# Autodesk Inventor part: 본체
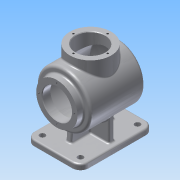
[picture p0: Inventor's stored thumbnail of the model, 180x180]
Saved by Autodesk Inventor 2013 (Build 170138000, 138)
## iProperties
Created: 2016-09
Part Number: 본체
Material: 알루미늄 6061
Document SubType Name: Modeling
Designer: Administrator
Density: 2.71 g/cm^3
Mass: 972.179 g
Surface Area: 1283.63 cm^2
Volume: 358.738 cm^3
Author: Administrator
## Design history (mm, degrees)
sketch "스케치1"
  geometry: L1 (-67.5, 50)-(67.5, 50); L2 (67.5, 50)-(67.5, -50); L3 (67.5, -50)-(-67.5, -50); L4 (-67.5, -50)-(-67.5, 50); L5 (67.5, -50)-(-67.5, 50); 2 further points
  constraints: 10 end point, 2 parallel, 1 coincident, 1 horizontal, 1 midpoint, 1 perpendicular
  dimensions: "d0" = 135 distance of L1.start L1.end; "d2" = 100 distance of L1.end L2.end
extrude "돌출1" new body sketch "스케치1" distance "d3" = 10; taper "d4" = 0 deg
fillet "모깎기1" dims "d5" = 15
hole "구멍1" diameter "d8" = 10; stored, may be unused: countersink angle "d12" = 90 deg, drill point angle "d14" = 0 deg; dims "d6" = 10, "d7" = 10, "d9" = 6, "d10" = 4, "d11" = 2, "d13" = 8
hole "구멍2" diameter "d17" = 10; stored, may be unused: countersink angle "d21" = 90 deg, drill point angle "d23" = 0 deg; dims "d15" = 10, "d16" = 10, "d18" = 6, "d19" = 4, "d20" = 2, "d22" = 8
hole "구멍3" diameter "d26" = 10; stored, may be unused: countersink angle "d30" = 90 deg, drill point angle "d32" = 0 deg; dims "d24" = 10, "d25" = 10, "d27" = 6, "d28" = 4, "d29" = 2, "d31" = 8
hole "구멍4" diameter "d35" = 10; stored, may be unused: countersink angle "d39" = 90 deg, drill point angle "d41" = 0 deg; dims "d33" = 10, "d34" = 10, "d36" = 6, "d37" = 4, "d38" = 2, "d40" = 8
fillet "모깎기2" dims "d42" = 3
sketch "스케치3"
  geometry: L1 (-64.5, 10)-(64.5, 10) reference; L2 (67.5, 7)-(67.5, 0) reference; L3 (67.5, 0)-(-67.5, 0) reference; L4 (-67.5, 0)-(-67.5, 7) reference; L5 (0, 0)-(0, 82); L6 (-44, 132)-(46.374, 132); L7 (61, 132)-(61, 82); L8 (61, 82)-(-61, 82); L9 (-61, 82)-(-61, 132); L10 (-61, 120)-(-49, 120); L11 (-49, 120)-(-49, 127); L12 (46.374, 129)-(-44, 129); L13 (-46, 127)-(-46, 82); L14 (-61, 82)-(61, 82); A1 r 3 centre (-64.5, 7) between (-64.5, 10) and (-67.5, 7) reference; A2 r 3 centre (64.5, 7) between (67.5, 7) and (64.5, 10) reference; A3 r 115 centre (-54, 82) between (26.629, 0) and (35.672, 10); A4 r 115 centre (-54, 82) between (61, 82) and (50.937, 129.045); A5 r 112 centre (-54, 82) between (58, 82) and (48.199, 127.818); A6 r 2 centre (-44, 127) between (-44, 129) and (-46, 127); A7 r 2 centre (46.374, 127) between (48.199, 127.818) and (46.374, 129); A8 r 5 centre (-44, 127) between (-44, 132) and (-49, 127); A9 r 5 centre (46.374, 127) between (50.937, 129.045) and (46.374, 132); 3 further points
  constraints: 20 end point, 16 point on circle, 10 point on line, 9 tangent, 7 centre point, 5 perpendicular, 3 parallel, 2 equal radius, 1 collinear, 1 horizontal, 1 midpoint
  dimensions: "d44" = 82 distance of L5.end L5.start; "d45" = 122 distance of L9.end L7.start; "d47" = 76 diameter of L10 L8; "d48" = 100 diameter of L6 L8; "d50" = 115 radius of A4; "d51" = 3 radial gap between concentric circles of A4 A5; "d52" = 3 distance between parallel lines of L6 L12; "d53" = 3 distance between parallel lines of L11 L13; "d54" = 2 radius of A6; "d55" = 5 radius of A8; "d56" = 12 distance of L10.start L10.end
revolve "회전1" sketch "스케치3" stored, may be unused: angle "d57" = 90 deg
sketch "스케치4"
  geometry: L1 (-64.5, 10)-(64.5, 10) reference; L2 (67.5, 7)-(67.5, 0) reference; L3 (67.5, 0)-(-67.5, 0) reference; L4 (-67.5, 0)-(-67.5, 7) reference; L5 (-61, 44)-(-61, 120) reference; L6 (-61, 120)-(-49, 120) reference; L7 (-49, 120)-(-49, 127) reference; L8 (-44, 132)-(46.374, 132) reference; L9 (46.374, 32)-(-44, 32) reference; L10 (-49, 37)-(-49, 44) reference; L11 (-49, 44)-(-61, 44) reference; L12 (46.374, 129)-(-44, 129); L13 (-46, 127)-(-46, 117); L14 (-46, 117)-(-58, 117); L15 (-58, 117)-(-58, 82); L16 (-58, 82)-(58, 82); L17 (-46, 117)-(-46, 82); A1 r 3 centre (-64.5, 7) between (-64.5, 10) and (-67.5, 7) reference; A2 r 3 centre (64.5, 7) between (67.5, 7) and (64.5, 10) reference; A3 r 5 centre (-44, 127) between (-44, 132) and (-49, 127) reference; A4 r 5 centre (46.374, 127) between (50.937, 129.045) and (46.374, 132) reference; A5 r 115 centre (-54, 82) between (50.937, 34.955) and (50.937, 129.045) reference; A6 r 5 centre (46.374, 37) between (46.374, 32) and (50.937, 34.955) reference; A7 r 5 centre (-44, 37) between (-49, 37) and (-44, 32) reference; A8 r 2 centre (-44, 127) between (-44, 129) and (-46, 127); A9 r 112 centre (-54, 82) between (58, 82) and (48.199, 127.818); A10 r 2 centre (46.374, 127) between (48.199, 127.818) and (46.374, 129); 1 further point
  constraints: 12 end point, 6 point on circle, 3 centre point, 1 point on line, 3 other
  dimensions: "d58" = 3 distance between parallel lines of L12 L8
revolve "회전2" sketch "스케치4" stored, may be unused: angle "d59" = 90 deg
hole "구멍5" diameter "d62" = 54; stored, may be unused: countersink angle "d66" = 90 deg, drill point angle "d68" = 0 deg; dims "d60" = 10, "d61" = 10, "d63" = 6, "d64" = 4, "d65" = 2, "d67" = 20
node "작업 평면1"
sketch "스케치5"
  geometry: L1 (-46.374, 50)-(-46.374, -50) reference; L2 (49, 45)-(49, -45) reference; L3 (52.5, 50)-(-52.5, 50) reference; L4 (44, -50)-(-46.374, -50) reference; C1 r 38 at (-1, 0)
  constraints: 1 centre point
  dimensions: "d70" = 76 diameter of C1; "d133" = 50 distance from line of L2 C1.centre; "d134" = 50 distance from line of L4 C1.centre
extrude "돌출2" join sketch "스케치5" stored distance "d71" = 10; taper "d72" = 0 deg
hole "구멍6" diameter "d75" = 54; stored, may be unused: countersink angle "d79" = 90 deg, drill point angle "d81" = 0 deg; dims "d73" = 10, "d74" = 10, "d76" = 6, "d77" = 4, "d78" = 2, "d80" = 50
fillet "모깎기3" dims "d82" = 3
chamfer "모따기1" distance "d83" = 1; stored, may be unused: second distance "d84" = 2, angle "d85" = 45 deg
sketch "스케치6"
  geometry: L1 (-31.5, 0)-(33.5, 0); C1 r 28 at (0, 0) reference; C2 r 38 at (0, 0) reference; 3 further points
  constraints: 2 coincident, 2 end point, 1 horizontal, 1 midpoint
  dimensions: "d86" = 65 distance of L1.start L1.end
hole "구멍7" sketch "스케치6" at (-31.5, 0) diameter "d88" = 3.459; stored, may be unused: countersink angle "d92" = 90 deg, drill point angle "d94" = 118 deg; dims "d89" = 8, "d90" = 4, "d91" = 2, "d93" = 10
sketch "스케치7"
  geometry: L1 (75, 47.359)-(82, 47.359) reference; L2 (82, 47.359)-(82, -47.359) reference; L3 (82, -47.359)-(75, -47.359) reference; L4 (72, -43.471)-(72, 43.471) reference; L5 (32.5, 0)-(-32.5, 0); C1 r 28 at (0, 0) reference; C2 r 38 at (0, 0) reference; 3 further points
  constraints: 2 coincident, 2 end point, 1 midpoint, 1 perpendicular, 2 other
  dimensions: "d98" = 65 distance of L5.start L5.end
hole "구멍8" sketch "스케치7" at (-32.5, 0) diameter "d100" = 3.459; stored, may be unused: countersink angle "d104" = 90 deg, drill point angle "d106" = 118 deg; dims "d101" = 8, "d102" = 4, "d103" = 2, "d105" = 10
sketch "스케치9"
  geometry: L1 (-46, 127)-(-46, 109) reference; L2 (-46, 109)-(-60, 109) reference; L3 (-60, 109)-(-61, 110) reference; L4 (-61, 110)-(-61, 112.77) reference; L5 (-61, 112.77)-(-51, 112.77) reference; L6 (-51, 112.77)-(-49.961, 114.5) reference; L7 (-49.961, 114.5)-(-51, 116.23) reference; L8 (-51, 116.23)-(-61, 116.23) reference; L9 (-61, 116.23)-(-61, 120) reference; L10 (-61, 120)-(-52, 120) reference; L11 (-49, 123)-(-49, 127) reference; L12 (-44, 132)-(-40, 132) reference; L13 (-37, 135)-(-37, 147) reference; L14 (-37, 147)-(-32.23, 147) reference; L15 (-32.23, 147)-(-32.23, 137) reference; L16 (-32.23, 137)-(-30.5, 135.961) reference; L17 (-30.5, 135.961)-(-28.771, 137) reference; L18 (-28.771, 137)-(-28.771, 147) reference; L19 (-28.771, 147)-(-27, 147) reference; L20 (-27, 147)-(-26, 146) reference; L21 (-26, 146)-(-26, 129) reference; L22 (-26, 129)-(-44, 129) reference; L23 (-64.5, 10)-(64.5, 10) reference; L24 (46.374, 32)-(-44, 32) reference; L25 (-49, 37)-(-49, 41) reference; L26 (-52, 44)-(-61, 44) reference; L27 (-61, 44)-(-61, 47.77) reference; L28 (-61, 47.77)-(-51, 47.77) reference; L29 (-51, 47.77)-(-49.961, 49.5) reference; L30 (-49.961, 49.5)-(-51, 51.229) reference; L31 (-51, 51.229)-(-61, 51.229) reference; L32 (-61, 51.229)-(-61, 54) reference; L33 (-61, 54)-(-60, 55) reference; L34 (-60, 55)-(-46, 55) reference; L35 (-46, 55)-(-46, 37) reference; L36 (-44, 35)-(46.374, 35) reference; L37 (46.374, 129)-(28, 129) reference; L38 (28, 129)-(28, 146) reference; L39 (28, 146)-(29, 147) reference; L40 (29, 147)-(30.77, 147) reference; L41 (30.77, 147)-(30.77, 137) reference; L42 (30.77, 137)-(32.5, 135.961) reference; L43 (32.5, 135.961)-(34.23, 137) reference; L44 (34.23, 137)-(34.23, 147) reference; L45 (34.23, 147)-(39, 147) reference; L46 (39, 147)-(39, 135) reference; L47 (42, 132)-(46.374, 132) reference; L48 (67.5, 7)-(67.5, 0) reference; L49 (67.5, 0)-(-67.5, 0) reference; L50 (-67.5, 0)-(-67.5, 7) reference; L51 (-38.075, 32)-(-40, 10); L52 (0, 0)-(0, 67.844); L53 (38.075, 32)-(40, 10); A1 r 2 centre (-44, 127) between (-44, 129) and (-46, 127) reference; A2 r 3 centre (-52, 123) between (-52, 120) and (-49, 123) reference; A3 r 5 centre (-44, 127) between (-44, 132) and (-49, 127) reference; A4 r 3 centre (-64.5, 7) between (-64.5, 10) and (-67.5, 7) reference; A5 r 5 centre (-44, 37) between (-49, 37) and (-44, 32) reference; A6 r 3 centre (-52, 41) between (-49, 41) and (-52, 44) reference; A7 r 2 centre (-44, 37) between (-46, 37) and (-44, 35) reference; A8 r 2 centre (46.374, 37) between (46.374, 35) and (48.199, 36.182) reference; A9 r 112 centre (-54, 82) between (48.199, 36.182) and (48.199, 127.818) reference; A10 r 2 centre (46.374, 127) between (48.199, 127.818) and (46.374, 129) reference; A11 r 5 centre (46.374, 127) between (50.937, 129.045) and (46.374, 132) reference; A12 r 115 centre (-54, 82) between (50.937, 34.955) and (50.937, 129.045) reference; A13 r 5 centre (46.374, 37) between (46.374, 32) and (50.937, 34.955) reference; A14 r 3 centre (64.5, 7) between (67.5, 7) and (64.5, 10) reference
  constraints: 6 end point, 2 point on line, 2 symmetric about line, 1 parallel, 2 other
  dimensions: "d114" = 40 horizontal distance of L52.start L51.end; "d115" = 95 deg angle of L23 L51
  node "절단 모서리 투영6"
node "작업 평면2"
sketch "스케치10"
  geometry: L1 (43.292, 7)-(43.292, 0) reference; L2 (43.292, 0)-(-43.292, 0) reference; L3 (-43.292, 0)-(-43.292, 7) reference; L4 (-35, 9.958)-(35, 9.958) reference; L5 (35, 0)-(-35, 0) reference; L6 (-26.132, 94.195)-(26.132, 94.195); L7 (26.132, 94.195)-(26.132, 69.805); L8 (26.132, 69.805)-(-26.132, 69.805); L9 (-26.132, 69.805)-(-26.132, 94.195); L10 (-26.132, 82)-(26.132, 82); L11 (0, 94.195)-(0, 69.805); L12 (0, 82)-(0, 0); C1 r 50 at (0, 82) reference
  constraints: 6 end point, 5 midpoint, 2 collinear, 4 other
feature "엠보싱1" sketch "스케치10" dims "d0" = 135, "d2" = 100, "d24" = 10, "d25" = 10, "d131" = 0.5, "d132" = 0
sketch "스케치11"
  geometry: L1 (-37.987, 115.603)-(-37.987, 147) reference; L2 (-37.987, 147)-(-32.911, 147) reference; L3 (-32.911, 147)-(-32.911, 137) reference; L4 (-30.089, 137)-(-30.089, 147) reference; L5 (-30.089, 147)-(-27.982, 147) reference; L6 (-27.982, 147)-(-26.981, 146) reference; L7 (-26.981, 146)-(-26.981, 120.484) reference; L8 (26.981, 120.484)-(26.981, 146) reference; L9 (26.981, 146)-(27.982, 147) reference; L10 (27.982, 147)-(30.089, 147) reference; L11 (30.089, 147)-(30.089, 137) reference; L12 (32.911, 137)-(32.911, 147) reference; L13 (32.911, 147)-(37.987, 147) reference; L14 (37.987, 147)-(37.987, 115.603) reference; L15 (50, 7)-(50, 0) reference; L16 (50, 0)-(-50, 0) reference; L17 (-50, 0)-(-50, 7) reference; L18 (-47, 10)-(47, 10) reference; L19 (-40, 52)-(-40, 10); L20 (40, 52)-(40, 10); L21 (0, 0)-(0, 82); A1 r 50 centre (0, 82) between (-38.668, 113.699) and (38.668, 113.699) reference; A2 r 47 centre (0, 82) between (-26.981, 120.484) and (26.981, 120.484) reference; A3 r 3 centre (47, 7) between (50, 7) and (47, 10) reference; A4 r 3 centre (-47, 7) between (-47, 10) and (-50, 7) reference
  constraints: 6 end point, 2 horizontal alignment, 2 perpendicular, 2 point on circle, 2 point on line, 1 parallel, 2 other
  dimensions: "d135" = 40 distance between parallel lines of L21 L19; "d136" = 40 distance between parallel lines of L20 L21
extrude "돌출4" join sketch "스케치11" stored distance "d137" = 10; taper "d138" = 0 deg
sketch "스케치12"
  geometry: L1 (-46, 127)-(-46, 109) reference; L2 (-46, 109)-(-60, 109) reference; L3 (-60, 109)-(-61, 110) reference; L4 (-61, 110)-(-61, 112.77) reference; L5 (-61, 112.77)-(-51, 112.77) reference; L6 (-51, 112.77)-(-49.961, 114.5) reference; L7 (-49.961, 114.5)-(-51, 116.23) reference; L8 (-51, 116.23)-(-61, 116.23) reference; L9 (-61, 116.23)-(-61, 120) reference; L10 (-61, 120)-(-52, 120) reference; L11 (-49, 123)-(-49, 127) reference; L12 (-44, 132)-(-40, 132) reference; L13 (-37, 135)-(-37, 147) reference; L14 (-37, 147)-(-32.23, 147) reference; L15 (-32.23, 147)-(-32.23, 137) reference; L16 (-32.23, 137)-(-30.5, 135.961) reference; L17 (-30.5, 135.961)-(-28.771, 137) reference; L18 (-28.771, 137)-(-28.771, 147) reference; L19 (-28.771, 147)-(-27, 147) reference; L20 (-27, 147)-(-26, 146) reference; L21 (-26, 146)-(-26, 129) reference; L22 (-26, 129)-(-44, 129) reference; L23 (46.374, 129)-(28, 129) reference; L24 (28, 129)-(28, 146) reference; L25 (28, 146)-(29, 147) reference; L26 (29, 147)-(30.77, 147) reference; L27 (30.77, 147)-(30.77, 137) reference; L28 (30.77, 137)-(32.5, 135.961) reference; L29 (32.5, 135.961)-(34.23, 137) reference; L30 (34.23, 137)-(34.23, 147) reference; L31 (34.23, 147)-(39, 147) reference; L32 (39, 147)-(39, 135) reference; L33 (42, 132)-(46.374, 132) reference; L34 (60.952, 85.339)-(61.452, 85.339) reference; L35 (61.467, 84.759)-(60.967, 84.759) reference; L36 (46.374, 32)-(5, 32) reference; L37 (5, 32)-(5, 10) reference; L38 (5, 10)-(64.5, 10) reference; L39 (67.5, 7)-(67.5, 0) reference; L40 (67.5, 0)-(-67.5, 0) reference; L41 (-67.5, 0)-(-67.5, 7) reference; L42 (-64.5, 10)-(-5, 10) reference; L43 (-5, 10)-(-5, 32) reference; L44 (-5, 32)-(-44, 32) reference; L45 (-49, 37)-(-49, 41) reference; L46 (-52, 44)-(-61, 44) reference; L47 (-61, 44)-(-61, 47.77) reference; L48 (-61, 47.77)-(-51, 47.77) reference; L49 (-51, 47.77)-(-49.961, 49.5) reference; L50 (-49.961, 49.5)-(-51, 51.229) reference; L51 (-51, 51.229)-(-61, 51.229) reference; L52 (-61, 51.229)-(-61, 54) reference; L53 (-61, 54)-(-60, 55) reference; L54 (-60, 55)-(-46, 55) reference; L55 (-46, 55)-(-46, 37) reference; L56 (-44, 35)-(46.374, 35) reference; L57 (-38.075, 32)-(-40, 10); L58 (0, 0.971)-(0, 54); L59 (38.075, 32)-(40, 10); A1 r 2 centre (-44, 127) between (-44, 129) and (-46, 127) reference; A2 r 3 centre (-52, 123) between (-52, 120) and (-49, 123) reference; A3 r 5 centre (-44, 127) between (-44, 132) and (-49, 127) reference; A4 r 112 centre (-54, 82) between (48.199, 36.182) and (48.199, 127.818) reference; A5 r 2 centre (46.374, 127) between (48.199, 127.818) and (46.374, 129) reference; A6 r 5 centre (46.374, 127) between (50.937, 129.045) and (46.374, 132) reference; A7 r 115 centre (-54, 82) between (60.952, 85.339) and (50.937, 129.045) reference; A8 r 115.5 centre (-54, 82) between (61.467, 84.759) and (61.452, 85.339) reference; A9 r 115 centre (-54, 82) between (50.937, 34.955) and (60.967, 84.759) reference; A10 r 5 centre (46.374, 37) between (46.374, 32) and (50.937, 34.955) reference; A11 r 3 centre (64.5, 7) between (67.5, 7) and (64.5, 10) reference; A12 r 3 centre (-64.5, 7) between (-64.5, 10) and (-67.5, 7) reference; A13 r 5 centre (-44, 37) between (-49, 37) and (-44, 32) reference; A14 r 3 centre (-52, 41) between (-49, 41) and (-52, 44) reference; A15 r 2 centre (-44, 37) between (-46, 37) and (-44, 35) reference; A16 r 2 centre (46.374, 37) between (46.374, 35) and (48.199, 36.182) reference; 1 further point
  constraints: 6 end point, 2 point on line, 2 symmetric about line, 1 perpendicular, 2 other
  dimensions: "d139" = 40 horizontal distance of point (0, 0) L57.end; "d140" = 95 deg angle of L42 L57
  node "절단 모서리 투영9"
feature "리브3" dims "d141" = 1, "d142" = 10, "d143" = 0, "d144" = 0, "d145" = 1, "d146" = 1
feature "리브4" dims "d147" = 1, "d148" = 10, "d149" = 0, "d150" = 0, "d151" = 1, "d152" = 1
fillet "모깎기6" dims "d153" = 3
fillet "모깎기7" dims "d154" = 3
node "솔리드1"
pattern_circular "원형 패턴1" dims angle "d96" = 360 deg
pattern_circular "원형 패턴2" dims angle "d108" = 360 deg
node "절단 모서리 투영1"
node "절단 모서리 투영2"
node "절단 모서리 투영3"
node "절단 모서리 투영4"
node "절단 모서리 투영7"
node "절단 모서리 투영8"
other parameters: "d49" = 115, "d69" = 147, "d130" = -65
